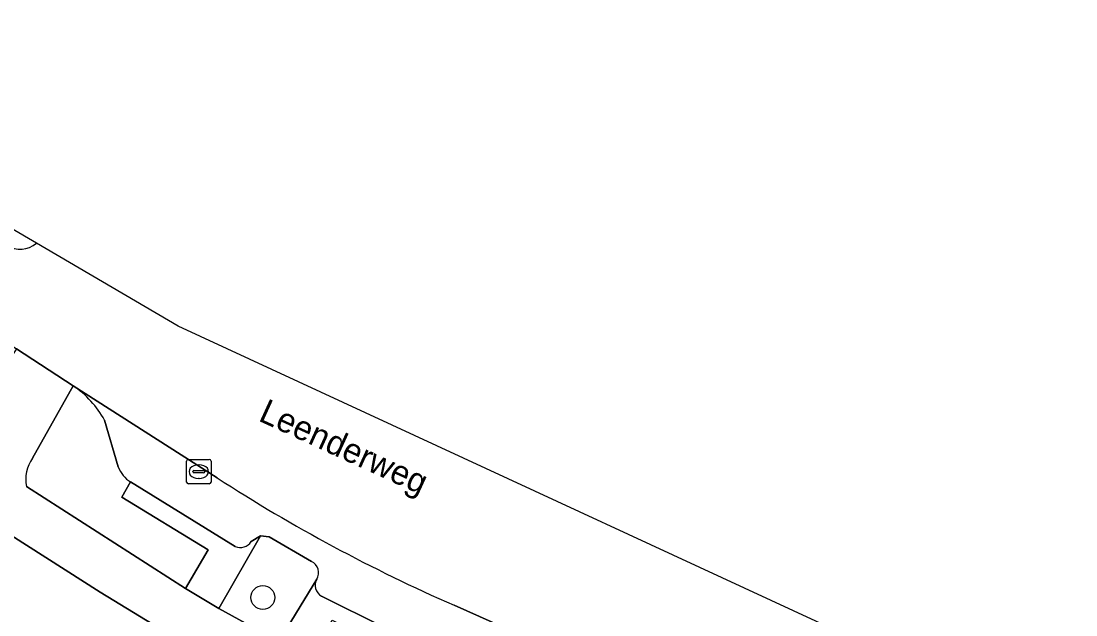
# Model space of a CAD drawing. Extents: x 161838 to 162344, y 381620 to 382160.
# Drawn here: x 162156.85 to 162200.09, y 381831.01 to 381855.34 of the extents above; entities that cross this region are included whole.
import ezdxf

# ---------------------------------------------------------------- set-up
doc = ezdxf.new("R2010")
doc.units = 0
for name, color, linetype in [('IMGEO_Berm_groen', 7, 'Continuous'), ('IMGEO_Boom', 7, 'Continuous'), ('IMGEO_Kolk', 7, 'Continuous'), ('IMGEO_Openbare_ruimte_label', 7, 'Continuous'), ('IMGEO_Parkeervlak_open', 7, 'Continuous'), ('IMGEO_Rijbaan_lokaal_gesloten', 7, 'Continuous'), ('IMGEO_Verkeerseiland_open', 7, 'Continuous'), ('IMGEO_Voetpad_gesloten', 7, 'Continuous'), ('IMGEO_Voetpad_open', 7, 'Continuous')]:
    doc.layers.add(name, color=color, linetype=linetype)

msp = doc.modelspace()

# ---------------------------------------------------------------- linework, layer by layer
at = {"layer": 'IMGEO_Berm_groen'}
for points in [[(162158.986, 381840.398), (162157.312, 381837.428)], [(162160.832, 381837.072), (162160.272, 381838.989)], [(162157.069, 381836.267), (162163.589, 381832.092), (162164.515, 381833.671), (162160.982, 381835.828), (162161.335, 381836.455)], [(162168.758, 381833.193), (162167.02, 381834.201), (162166.661, 381834.249), (162164.958, 381831.269), (162167.418, 381829.919), (162168.968, 381832.475)]]:
    msp.add_lwpolyline(points, dxfattribs=at)
for centre, radius, start, end in [((162156.493, 381836.831), 4.352, 29.7263, 55.0473), ((162158.528, 381836.568), 1.489, 144.7141, 191.6429), ((162161.977, 381837.492), 1.22, 200.1421, 238.2341), ((162168.54, 381832.74), 0.503, 328.2451, 64.3611)]:
    msp.add_arc(centre, radius, start, end, dxfattribs=at)
at = {"layer": 'IMGEO_Boom'}
msp.add_circle((162166.756, 381831.718), 0.489, dxfattribs=at)
at = {"layer": 'IMGEO_Kolk'}
for p, q in [((162163.633, 381836.451), (162163.633, 381837.303)), ((162163.708, 381837.377), (162164.56, 381837.377)), ((162164.121, 381837.157), (162164.146, 381837.157)), ((162164.634, 381837.303), (162164.634, 381836.451)), ((162163.892, 381836.871), (162163.892, 381836.883)), ((162164.33, 381836.834), (162163.932, 381836.834)), ((162163.935, 381836.92), (162164.333, 381836.92)), ((162164.144, 381836.597), (162164.119, 381836.597)), ((162164.376, 381836.883), (162164.376, 381836.871)), ((162164.56, 381836.377), (162163.708, 381836.377))]:
    msp.add_line(p, q, dxfattribs=at)
for points in [[(162163.633, 381836.451), (162163.633, 381837.303)], [(162163.708, 381837.377), (162164.56, 381837.377)], [(162164.634, 381837.303), (162164.634, 381836.451)], [(162164.56, 381836.377), (162163.708, 381836.377)]]:
    msp.add_lwpolyline(points, dxfattribs=at)
for centre, radius, start, end in [((162163.71, 381837.301), 0.0765, 91.552, 178.448), ((162163.71, 381837.301), 0.0765, 91.552, 178.448), ((162164.558, 381837.301), 0.0765, 1.552, 88.448), ((162164.558, 381837.301), 0.0765, 1.552, 88.448), ((162163.932, 381836.88), 0.0403, 85.8775, 175.7526), ((162163.929, 381836.87), 0.0366, 178.938, 274.7102), ((162164.333, 381836.877), 0.043, 264.8664, 352.4533), ((162164.337, 381836.882), 0.0386, 1.7309, 96.639), ((162163.71, 381836.453), 0.0765, 181.552, 268.448), ((162163.71, 381836.453), 0.0765, 181.552, 268.448), ((162164.558, 381836.453), 0.0765, 271.552, 358.448), ((162164.558, 381836.453), 0.0765, 271.552, 358.448)]:
    msp.add_arc(centre, radius, start, end, dxfattribs=at)
for centre, major_axis, ratio, start_param, end_param in [((162164.12, 381836.877), (-0.387, 0.002), 0.722429, 4.712389, 7.853982), ((162164.145, 381836.877), (-0.39, 0.002), 0.717154, 1.570796, 4.712389)]:
    msp.add_ellipse(centre, major_axis=major_axis, ratio=ratio, start_param=start_param, end_param=end_param, dxfattribs=at)
at = {"layer": 'IMGEO_Parkeervlak_open'}
for points in [[(162164.889, 381836.622), (162158.986, 381840.398)], [(162160.272, 381838.989), (162160.832, 381837.072)], [(162161.335, 381836.455), (162165.622, 381833.804)], [(162166.28, 381834.01), (162166.661, 381834.249), (162167.02, 381834.201), (162168.758, 381833.193)], [(162169.166, 381831.776), (162171.748, 381830.494), (162186.408, 381823.952), (162186.818, 381823.858), (162187.175, 381823.914), (162188.774, 381824.481)], [(162189.905, 381824.561), (162174.607, 381831.399)]]:
    msp.add_lwpolyline(points, dxfattribs=at)
for centre, radius, start, end in [((162156.493, 381836.831), 4.352, 29.7263, 55.0473), ((162161.977, 381837.492), 1.22, 200.1421, 238.2341), ((162201.636, 381893.343), 67.584, 237.06213, 246.4257), ((162165.826, 381834.307), 0.542, 247.9167, 326.8509), ((162168.54, 381832.74), 0.503, 328.2451, 64.3611), ((162169.405, 381832.221), 0.505, 149.8716, 241.7592)]:
    msp.add_arc(centre, radius, start, end, dxfattribs=at)
at = {"layer": 'IMGEO_Rijbaan_lokaal_gesloten'}
for points in [[(162107.401, 381891.02), (162110.364, 381886.414), (162113.19, 381882.377), (162116.706, 381877.858), (162119.709, 381874.255), (162122.966, 381870.633), (162126.414, 381866.991), (162131.726, 381861.745), (162132.386, 381861.014), (162136.567, 381857.218), (162142.172, 381852.464), (162147.466, 381848.311), (162150.594, 381846.009), (162156.657, 381841.909), (162158.986, 381840.398), (162164.889, 381836.622)], [(162174.607, 381831.399), (162189.905, 381824.561), (162190.345, 381824.364), (162197.539, 381821.152), (162203.924, 381818.301), (162204.044, 381818.258), (162266.265, 381790.084), (162269.159, 381788.667), (162270.414, 381791.728), (162270.956, 381793.049), (162163.289, 381842.84), (162157.474, 381846.239)]]:
    msp.add_lwpolyline(points, dxfattribs=at)
for centre, radius, start, end in [((162156.805, 381847.021), 1.029, 238.3429, 310.5487), ((162201.636, 381893.343), 67.584, 237.06213, 246.4257)]:
    msp.add_arc(centre, radius, start, end, dxfattribs=at)
at = {"layer": 'IMGEO_Verkeerseiland_open'}
msp.add_lwpolyline([(162157.474, 381846.239), (162154.309, 381848.089), (162152.862, 381849.169), (162152.812, 381849.099)], dxfattribs=at)
msp.add_arc((162156.805, 381847.021), 1.029, 238.3429, 310.5487, dxfattribs=at)
at = {"layer": 'IMGEO_Voetpad_gesloten'}
for points in [[(162125.545, 381859.011), (162130.429, 381854.037), (162134.882, 381849.978), (162140.263, 381845.513), (162147.552, 381840.181), (162154.18, 381835.7), (162160.086, 381831.935), (162165.238, 381828.801), (162168.761, 381826.912), (162197.313, 381814.891), (162266.754, 381783.434), (162271.828, 381781.089), (162275.072, 381778.709), (162277.759, 381775.733), (162280.091, 381772.447), (162282.076, 381768.974), (162284.268, 381764.473), (162289.497, 381752.523), (162295.191, 381737.537), (162297.128, 381732.914), (162299.208, 381728.355), (162301.472, 381723.885)], [(162157.312, 381837.428), (162158.986, 381840.398), (162156.657, 381841.909), (162154.592, 381838.844)], [(162200.882, 381815.518), (162191.564, 381819.539), (162185.978, 381821.85), (162184.486, 381822.474), (162172.861, 381827.333), (162168.74, 381829.184), (162167.418, 381829.919), (162164.958, 381831.269), (162163.589, 381832.092), (162157.069, 381836.267)]]:
    msp.add_lwpolyline(points, dxfattribs=at)
msp.add_arc((162158.528, 381836.568), 1.489, 144.7141, 191.6429, dxfattribs=at)
at = {"layer": 'IMGEO_Voetpad_open'}
for points in [[(162168.761, 381826.912), (162165.238, 381828.801), (162160.086, 381831.935), (162154.18, 381835.7), (162147.552, 381840.181), (162140.263, 381845.513), (162134.882, 381849.978), (162133.845, 381846.181), (162136.021, 381844.574), (162140.849, 381840.974), (162145.582, 381837.445), (162150.263, 381833.955), (162155.076, 381830.366), (162161.549, 381827.655), (162168.182, 381824.878), (162174.599, 381822.191), (162181.034, 381819.497), (162188.075, 381816.549), (162188.305, 381815.945), (162192.878, 381813.922), (162195.978, 381812.551), (162198.869, 381811.272), (162199.091, 381811.761), (162206.304, 381808.493)], [(162165.622, 381833.804), (162161.335, 381836.455), (162160.982, 381835.828), (162164.515, 381833.671), (162163.589, 381832.092), (162164.958, 381831.269), (162166.661, 381834.249), (162166.28, 381834.01)], [(162168.968, 381832.475), (162167.418, 381829.919), (162168.74, 381829.184), (162169.605, 381830.784), (162172.352, 381829.469), (162185.071, 381823.796), (162184.486, 381822.474), (162185.978, 381821.85), (162186.818, 381823.858), (162186.408, 381823.952), (162171.748, 381830.494), (162169.166, 381831.776)]]:
    msp.add_lwpolyline(points, dxfattribs=at)
for centre, radius, start, end in [((162165.826, 381834.307), 0.542, 247.9167, 326.8509), ((162169.405, 381832.221), 0.505, 149.8716, 241.7592)]:
    msp.add_arc(centre, radius, start, end, dxfattribs=at)

# ---------------------------------------------------------------- texts
at = {"layer": 'IMGEO_Openbare_ruimte_label'}
msp.add_text('Leenderweg', height=1, rotation=335.409, dxfattribs=at).set_placement((162166.535, 381838.982))

doc.saveas('drawing.dxf')
